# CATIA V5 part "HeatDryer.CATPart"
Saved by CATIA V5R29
Part number: HeatDryer
Bounding box of the stored display mesh (mm): x -740 to 572.872, y -135 to 1965, z -385.453 to 1865.453
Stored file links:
  C:\가치같이\SmartFactory_HeatDryer\HeatDryer.CATPart
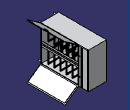
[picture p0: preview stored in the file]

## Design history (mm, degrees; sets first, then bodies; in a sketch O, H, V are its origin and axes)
Set1
  Plane1: type Offset, RefPlane face of Solid1, Offset 200, reversed
  Sketch1 on Plane1, origin (0, 235, 0), H (1, 0, 0), V (0, 0, 1)
    line L1 (-690, 1388) -> (-50, 1388)
    line L2 (-50, 1388) -> (-50, 888)
    line L3 (-50, 888) -> (-690, 888)
    line L4 (-690, 888) -> (-690, 918)
    line L5 (-690, 918) -> (-640, 918)
    line L6 (-640, 918) -> (-640, 1358)
    line L7 (-640, 1358) -> (-690, 1358)
    point P8 (-690, 1358)
    line L8 (-690, 1358) -> (-690, 1388)
    reference projected line E1 (-690, 1438) -> (-690, 42) from edge [face of Solid1 | face of Solid1]
    reference projected line E2 (-690, 1438) -> (0, 1438) from edge [face of Solid1 | face of Solid1]
    reference projected point E3 (0, 838) from edge [face of Solid1 | face of Solid1]
    reference projected line E4 (0, 1459.122) -> (0, 20.878) from edge [face of Solid1 | face of Solid1]
    point P9 (-610, 1358)
    line L9 (-610, 1358) -> (-80, 1358)
    line L10 (-80, 1358) -> (-80, 918)
    line L11 (-80, 918) -> (-610, 918)
    line L12 (-610, 918) -> (-610, 1358)
    point P11 (-80, 918)
    distance L1 E2 = 50
    distance L7 L1 = 30
    length L4 = 30
    length L7 = 50
    distance L3 E3 = 50
    distance L2 E4 = 50
    distance L10 L2 = 30
    distance L12 L6 = 30
    length L9 = 530 (reference)
    length L6 = 440 (reference)
    horizontal: L1 H, L3 H, L5 H, L7 H, L9 H, L11 H
    vertical: L2 V, L4 V, L6 V, L8 V, L10 V, L12 V
    coincidence: P8 L4, L8 L4, L8 E1, P9 L7, P11 L5
Body1 "Part 15" (main body)
  Solid1: solid without history
  Pad1: profile Sketch1, direction (0, 1, 0), length 30
  Plane2: type Between, Element1 face of Solid1, Element2 face of Solid1, Ratio 0.5
  RectPattern1: of Pad1, direction 1 instances 5, spacing 250, along edge [face of Solid1 | face of Solid1] reversed
  Mirror1: of Pad1, about Plane2
  Mirror2: of RectPattern1, about Plane2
